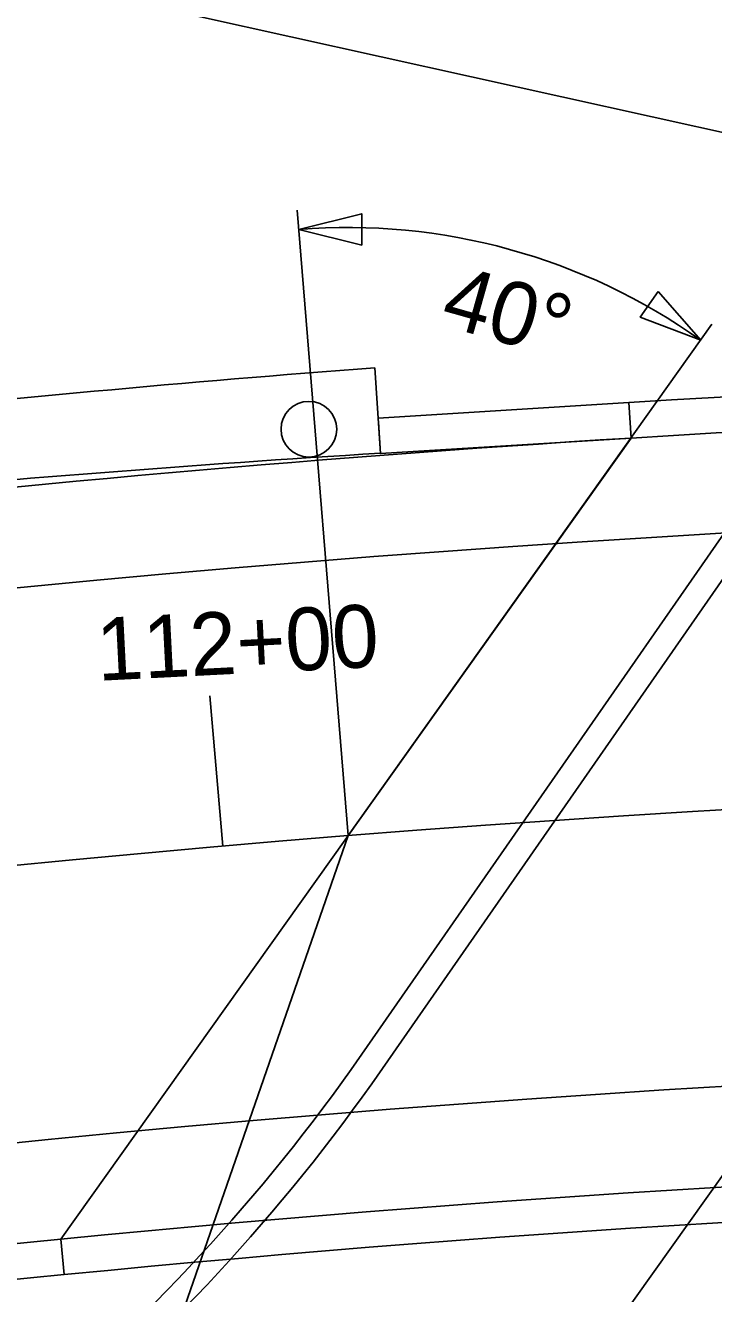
# Model space of a CAD drawing. Extents: x 1385284 to 1385995, y 1975154 to 1975620.
# Drawn here: x 1385446.2 to 1385473.7, y 1975469.1 to 1975519.6 of the extents above; entities that cross this region are included whole.
import ezdxf

# ---------------------------------------------------------------- set-up
doc = ezdxf.new("R2010")
doc.units = 0
for name, color, linetype in [('B-Super-Deck', 7, 'Continuous'), ('Default', 7, 'Continuous'), ('R_Bridge', 7, 'Continuous'), ('R_Guardrail', 7, 'Continuous'), ('R_Horz Alg', 7, 'Continuous'), ('R_Horz Alg Annot', 7, 'Continuous'), ('R_Horz Alg Stationing', 7, 'Continuous'), ('R_Proposed Const Limits', 7, 'Continuous'), ('R_Proposed Road', 7, 'Continuous'), ('R_Shld', 7, 'Continuous')]:
    doc.layers.add(name, color=color, linetype=linetype)

msp = doc.modelspace()

# ---------------------------------------------------------------- linework, layer by layer
at = {"layer": 'B-Super-Deck'}
for p, q in [((1385460.303, 1975503.99), (1385470.284, 1975504.61)), ((1385460.313, 1975503.823), (1385460.391, 1975502.576)), ((1385460.391, 1975502.576), (1385470.371, 1975503.196)), ((1385437.707, 1975470.297), (1385447.659, 1975471.279)), ((1385437.846, 1975468.888), (1385447.798, 1975469.869))]:
    msp.add_line(p, q, dxfattribs=at)
at = {"layer": 'Default'}
for p, q in [((1385459.222, 1975478.038), (1385485.092, 1975515.258)), ((1385485.913, 1975514.687), (1385460.044, 1975477.467)), ((1385457.08, 1975512.277), (1385459.101, 1975487.359)), ((1385459.101, 1975487.359), (1385473.596, 1975507.728)), ((1385470.371, 1975503.196), (1385470.284, 1975504.61)), ((1385447.659, 1975471.279), (1385470.371, 1975503.196)), ((1385459.101, 1975487.359), (1385470.371, 1975503.196)), ((1385459.101, 1975487.359), (1385417.983, 1975368.797)), ((1385447.659, 1975471.279), (1385447.798, 1975469.869))]:
    msp.add_line(p, q, dxfattribs=at)
for points in [[(1385459.643, 1975510.878), (1385457.143, 1975511.503), (1385459.643, 1975512.128)], [(1385471.454, 1975509.038), (1385473.146, 1975507.095), (1385470.738, 1975508.013)]]:
    msp.add_lwpolyline(points, close=True, dxfattribs=at)
for centre, radius, start, end in [((1385468.803, 1975526.863), 40, 324.5634, 101.9984), ((1385468.803, 1975526.863), 39, 324.5634, 101.9984), ((1385468.803, 1975526.863), 21, 324.5634, 101.9984), ((1385468.803, 1975526.863), 20, 324.5634, 101.9984), ((1385459.101, 1975487.359), 24.223, 54.5634, 94.6384), ((1385398.122, 1975521.532), 75, 293.41039, 324.56338), ((1385398.122, 1975521.532), 76, 293.41039, 324.56338)]:
    msp.add_arc(centre, radius, start, end, dxfattribs=at)
at = {"layer": 'R_Bridge'}
for p, q in [((1385470.284, 1975504.61), (1385470.371, 1975503.196)), ((1385470.371, 1975503.196), (1385447.659, 1975471.279)), ((1385447.798, 1975469.869), (1385447.659, 1975471.279))]:
    msp.add_line(p, q, dxfattribs=at)
for radius, start, end in [(710.911, 84.79144, 93.554346), (709.494, 84.79144, 93.554346), (679.494, 86.221345, 95.633125), (678.078, 86.221345, 95.633125)]:
    msp.add_arc((1385514.357, 1974795.066), radius, start, end, dxfattribs=at)
at = {"layer": 'R_Guardrail'}
msp.add_circle((1385457.541, 1975503.548), 1.109, dxfattribs=at)
msp.add_arc((1385504.568, 1974790.969), 712.994, 93.552431, 97.144548, dxfattribs=at)
at = {"layer": 'R_Horz Alg'}
msp.add_arc((1385514.357, 1974795.066), 694.494, 77.498258, 106.635112, dxfattribs=at)
at = {"layer": 'R_Horz Alg Annot'}
msp.add_line((1385315.54, 1975550.51), (1385664.693, 1975473.094), dxfattribs=at)
at = {"layer": 'R_Horz Alg Stationing'}
msp.add_line((1385454.119, 1975486.943), (1385453.598, 1975492.92), dxfattribs=at)
at = {"layer": 'R_Proposed Const Limits'}
msp.add_line((1385497.32, 1975506.57), (1385469.652, 1975467.69), dxfattribs=at)
msp.add_arc((1385468.803, 1975526.863), 35, 324.5634, 101.9984, dxfattribs=at)
at = {"layer": 'R_Proposed Road'}
for radius, end in [(705.494, 106.368381), (683.494, 106.910819)]:
    msp.add_arc((1385514.357, 1974795.066), radius, 77.498258, end, dxfattribs=at)
at = {"layer": 'R_Shld'}
msp.add_line((1385460.172, 1975505.999), (1385460.391, 1975502.576), dxfattribs=at)
for radius, start, end in [(712.994, 94.35844, 97.966039), (709.494, 93.554346, 106.273527)]:
    msp.add_arc((1385514.357, 1974795.066), radius, start, end, dxfattribs=at)

# ---------------------------------------------------------------- texts
at = {"layer": 'Default'}
for s, rotation, p in [('40%%d', 344.2207, (1385462.704, 1975507.726)), ('112+00', 2.8935, (1385449.141, 1975493.523))]:
    msp.add_text(s, height=2.5, rotation=rotation, dxfattribs=at).set_placement(p)

doc.saveas('drawing.dxf')
